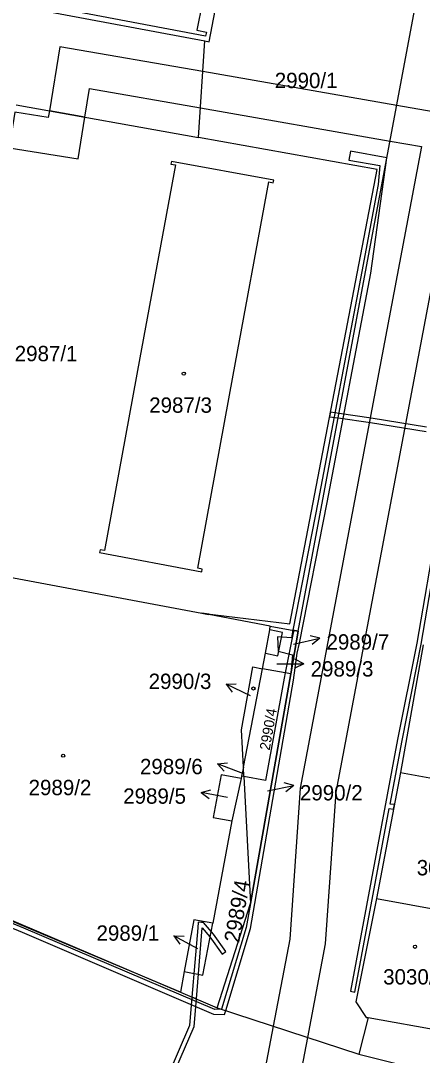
# Model space of a CAD drawing. Extents: x -756746 to -753363, y -1166406 to -1161727.
# Drawn here: x -755238.8 to -755194.3, y -1165348.4 to -1165233.9 of the extents above; entities that cross this region are included whole.
import ezdxf

# ---------------------------------------------------------------- set-up
doc = ezdxf.new("R2010")
doc.units = 0
for name, color, linetype in [('Hranice parcel', 7, 'Continuous'), ('Parcelní čísla', 7, 'Continuous'), ('Pop  PČ popisy', 7, 'Continuous'), ('Vnitřní kresba', 7, 'Continuous'), ('Věcná břemena k části', 7, 'Continuous'), ('Značky budov', 7, 'Continuous')]:
    doc.layers.add(name, color=color, linetype=linetype)

msp = doc.modelspace()

# ---------------------------------------------------------------- linework, layer by layer
at = {"layer": 'Hranice parcel'}
for p, q in [((-755208.07, -1165301.48), (-755195.18, -1165232.73)), ((-755219.11, -1165246.8), (-755218.43, -1165236.08)), ((-755239.33, -1165243.19), (-755219.11, -1165246.8)), ((-755247.99, -1165294), (-755218.74, -1165299.48)), ((-755211.17, -1165300.9), (-755218.74, -1165299.48)), ((-755211.22, -1165301.3), (-755211.17, -1165300.9)), ((-755211.17, -1165300.9), (-755208.57, -1165301.39)), ((-755208.9, -1165306.2), (-755208.07, -1165301.48)), ((-755208.07, -1165301.48), (-755208.57, -1165301.39)), ((-755194.22, -1165302.99), (-755196.74, -1165317.11)), ((-755214.15, -1165316.52), (-755212.03, -1165305.62)), ((-755213.36, -1165331.64), (-755208.9, -1165306.2)), ((-755209.51, -1165306.09), (-755212.03, -1165305.62)), ((-755208.9, -1165306.2), (-755209.51, -1165306.09)), ((-755214.15, -1165316.52), (-755214.35, -1165317.54)), ((-755214.09, -1165317.58), (-755214.15, -1165316.52)), ((-755214.4, -1165317.78), (-755215.44, -1165322.49)), ((-755214.35, -1165317.54), (-755214.4, -1165317.78)), ((-755214.09, -1165317.58), (-755214.35, -1165317.54)), ((-755214.09, -1165317.58), (-755213.36, -1165331.64)), ((-755196.74, -1165317.11), (-755199.39, -1165331.06)), ((-755215.44, -1165322.49), (-755217.54, -1165333.82)), ((-755217.05, -1165343.17), (-755213.36, -1165331.64)), ((-755220.7, -1165339.16), (-755221.13, -1165341.45)), ((-755221.13, -1165341.45), (-755217.05, -1165343.17)), ((-755217.05, -1165343.17), (-755201.37, -1165348.31)), ((-755201.37, -1165348.31), (-755184.78, -1165352.45))]:
    msp.add_line(p, q, dxfattribs=at)
for points in [[(-755215.57, -1165223.82), (-755214.31, -1165217.18), (-755232.9, -1165213.53), (-755236.61, -1165232.68), (-755218.43, -1165236.08)], [(-755218.43, -1165236.08), (-755217.92, -1165236.18), (-755215.57, -1165223.82)], [(-755218.74, -1165299.48), (-755209, -1165300.66), (-755199.33, -1165250.34), (-755219.11, -1165246.8)], [(-755211.33, -1165251.71), (-755210.84, -1165251.8), (-755210.78, -1165251.51), (-755222.11, -1165249.44), (-755222.17, -1165249.74), (-755221.68, -1165249.82), (-755225.61, -1165271.18), (-755229.54, -1165292.53), (-755230.03, -1165292.45), (-755230.09, -1165292.74), (-755218.76, -1165294.89), (-755218.7, -1165294.59), (-755219.2, -1165294.5), (-755215.27, -1165273.11), (-755211.33, -1165251.71)], [(-755252.61, -1165293.14), (-755254.82, -1165292.77), (-755254.61, -1165291.61), (-755260.25, -1165290.56), (-755260.48, -1165291.83), (-755272.55, -1165289.58), (-755272.53, -1165289.46), (-755280.36, -1165288), (-755280.39, -1165288.11), (-755287.48, -1165286.77), (-755287.69, -1165287.92), (-755287.95, -1165287.88), (-755288.05, -1165288.42), (-755290.9, -1165303.66), (-755292.09, -1165311.29), (-755257.06, -1165326.15), (-755221.13, -1165341.45)], [(-755212.03, -1165305.62), (-755211.7, -1165303.92), (-755210.34, -1165304.18), (-755209.8, -1165301.61), (-755211.22, -1165301.3)], [(-755208.57, -1165301.39), (-755208.65, -1165301.83), (-755209.51, -1165306.09)], [(-755214.15, -1165316.52), (-755214.37, -1165312.4), (-755213.08, -1165305.42), (-755212.03, -1165305.62)], [(-755209.51, -1165306.09), (-755209.62, -1165306.67), (-755211.71, -1165318.02), (-755214.09, -1165317.58)], [(-755221.13, -1165341.45), (-755254.32, -1165327.49), (-755292.48, -1165311.65)], [(-755214.4, -1165317.78), (-755216.62, -1165317.37), (-755217.48, -1165322.11), (-755215.44, -1165322.49)], [(-755196.74, -1165317.11), (-755185.38, -1165319.17), (-755184.13, -1165319.39), (-755182.45, -1165319.72), (-755176.65, -1165320.86), (-755173.46, -1165321.33), (-755170.61, -1165321.75)], [(-755199.39, -1165331.06), (-755201.67, -1165342.5), (-755200.54, -1165344.24), (-755200.31, -1165344.26), (-755201.37, -1165348.31)], [(-755199.39, -1165331.06), (-755191.7, -1165332.46), (-755188.08, -1165333.12), (-755185.23, -1165333.69), (-755184.75, -1165333.56)], [(-755217.54, -1165333.82), (-755219.62, -1165333.43), (-755220.7, -1165339.16)], [(-755220.7, -1165339.16), (-755218.62, -1165339.55), (-755217.54, -1165333.82)]]:
    msp.add_lwpolyline(points, dxfattribs=at)
at = {"layer": 'Pop  PČ popisy'}
for p, q in [((-755208.6, -1165302.91), (-755205.68, -1165302.24)), ((-755205.68, -1165302.24), (-755206.76, -1165301.97)), ((-755205.68, -1165302.24), (-755206.54, -1165302.95)), ((-755210.44, -1165305.07), (-755207.44, -1165305.07)), ((-755207.44, -1165305.07), (-755208.44, -1165304.57)), ((-755207.44, -1165305.07), (-755208.44, -1165305.57)), ((-755216.07, -1165307.34), (-755214.95, -1165307.31)), ((-755213.35, -1165308.61), (-755216.07, -1165307.34)), ((-755216.07, -1165307.34), (-755215.37, -1165308.22)), ((-755217.01, -1165316.16), (-755215.9, -1165316.05)), ((-755214.21, -1165317.23), (-755217.01, -1165316.16)), ((-755217.01, -1165316.16), (-755216.26, -1165316.98)), ((-755218.84, -1165319.33), (-755217.76, -1165319.03)), ((-755211.49, -1165319.14), (-755208.54, -1165318.57)), ((-755208.54, -1165318.57), (-755209.62, -1165318.27)), ((-755208.54, -1165318.57), (-755209.43, -1165319.25)), ((-755215.89, -1165319.9), (-755218.84, -1165319.33)), ((-755218.84, -1165319.33), (-755217.95, -1165320.01)), ((-755219.19, -1165336.63), (-755221.84, -1165335.22)), ((-755221.84, -1165335.22), (-755220.72, -1165335.25)), ((-755221.84, -1165335.22), (-755221.19, -1165336.13))]:
    msp.add_line(p, q, dxfattribs=at)
at = {"layer": 'Vnitřní kresba'}
for p, q in [((-755218.68, -1165231.81), (-755219.29, -1165234.92)), ((-755218.34, -1165235.56), (-755235.94, -1165232.26)), ((-755219.29, -1165234.92), (-755218.25, -1165235.12)), ((-755218.25, -1165235.12), (-755218.34, -1165235.56)), ((-755211.7, -1165303.92), (-755211.22, -1165301.3)), ((-755200.31, -1165344.26), (-755192.08, -1165345.73))]:
    msp.add_line(p, q, dxfattribs=at)
at = {"layer": 'Věcná břemena k části'}
for points in [[(-755228.32, -1165449.49), (-755213.31, -1165370.15), (-755218.48, -1165369.17), (-755217.54, -1165364.22), (-755210.64, -1165365.54), (-755209.98, -1165362.1), (-755207, -1165346.46), (-755205.03, -1165336.11), (-755203.87, -1165319.3), (-755189.72, -1165244.55), (-755197.15, -1165243.25), (-755218.65, -1165239.5), (-755234.49, -1165236.74), (-755235.64, -1165243.85)], [(-755231.7, -1165244.55), (-755231.19, -1165241.37), (-755218.9, -1165243.52), (-755197.89, -1165247.18), (-755194.42, -1165247.79), (-755207.85, -1165318.86), (-755209, -1165335.59), (-755210.83, -1165345.21), (-755213.83, -1165360.92), (-755219.88, -1165359.08), (-755220.8, -1165364.01), (-755222.4, -1165372.49), (-755217.98, -1165373.33), (-755233, -1165452.71)], [(-755235.64, -1165243.85), (-755231.7, -1165244.55)], [(-755278.26, -1165318.42), (-755238.67, -1165334.81), (-755217.44, -1165343.87), (-755216.24, -1165343.93), (-755216.1, -1165343.48), (-755213.36, -1165334.39), (-755208.58, -1165306.88), (-755208.19, -1165303.92), (-755207.91, -1165302.81), (-755204.87, -1165287.21), (-755200.03, -1165261.81), (-755198.24, -1165249.03), (-755202.29, -1165248.32), (-755202.46, -1165249.31), (-755199.04, -1165249.9), (-755199.21, -1165251.99), (-755201.01, -1165261.63), (-755205.85, -1165287.03), (-755208.65, -1165301.37), (-755208.07, -1165301.48), (-755208.9, -1165306.2), (-755213.36, -1165331.64), (-755213.84, -1165334.27), (-755216.57, -1165343.33), (-755217.32, -1165343.37), (-755238.47, -1165334.35), (-755278.06, -1165317.96)], [(-755193.85, -1165278.87), (-755200, -1165277.86), (-755203.55, -1165277.36), (-755204.5, -1165277.22), (-755204.59, -1165277.72), (-755203.64, -1165277.85), (-755200.07, -1165278.35), (-755193.89, -1165279.37)], [(-755192.68, -1165289.67), (-755194.93, -1165302.81), (-755197.07, -1165313.47), (-755202.28, -1165341.34), (-755201.79, -1165341.44), (-755197.98, -1165321.12), (-755197.51, -1165321.17), (-755197.42, -1165320.68), (-755197.88, -1165320.63), (-755196.57, -1165313.57), (-755194.44, -1165302.9), (-755192.19, -1165289.76)]]:
    msp.add_lwpolyline(points, dxfattribs=at)
for points in [[(-755235.64, -1165243.85), (-755235.76, -1165244.58), (-755239.46, -1165243.98), (-755240.1, -1165247.93), (-755232.45, -1165249.17), (-755231.7, -1165244.55)], [(-755218.49, -1165299.51), (-755218.74, -1165299.48), (-755218, -1165299.62), (-755217.98, -1165299.57)], [(-755208.9, -1165306.2), (-755208.07, -1165301.48), (-755208.65, -1165301.37), (-755208.81, -1165302.19), (-755210.35, -1165302.1), (-755210.29, -1165303.69), (-755208.72, -1165304.08)], [(-755219.84, -1165342), (-755219.35, -1165342.2), (-755218.7, -1165334.33), (-755217.85, -1165335.32), (-755216.51, -1165337.23), (-755216.1, -1165336.94), (-755217.45, -1165335.02), (-755218.55, -1165333.74), (-755218.78, -1165333.72), (-755219.15, -1165333.69), (-755219.2, -1165334.31)], [(-755223.07, -1165353.27), (-755219.6, -1165345.25), (-755219.35, -1165342.2), (-755219.84, -1165342), (-755220.1, -1165345.13), (-755223.65, -1165353.37), (-755220.77, -1165356.57), (-755220.4, -1165356.24)]]:
    msp.add_lwpolyline(points, close=True, dxfattribs=at)
at = {"layer": 'Značky budov'}
for centre in [(-755220.75, -1165272.94), (-755213.03, -1165307.82), (-755234.11, -1165315.26), (-755195.13, -1165336.42)]:
    msp.add_circle(centre, 0.175, dxfattribs=at)

# ---------------------------------------------------------------- texts
at = {"layer": 'Parcelní čísla'}
for s, p in [('2990/1', (-755210.67, -1165241.32)), ('2987/1', (-755239.48, -1165271.57)), ('2987/3', (-755224.58, -1165277.28)), ('2989/7', (-755204.94, -1165303.51)), ('2989/3', (-755206.69, -1165306.49)), ('2990/3', (-755224.64, -1165307.87)), ('2989/6', (-755225.6, -1165317.31)), ('2989/2', (-755237.94, -1165319.63)), ('2989/5', (-755227.46, -1165320.58)), ('2990/2', (-755207.88, -1165320.21)), ('3028', (-755194.94, -1165328.51)), ('2989/1', (-755230.42, -1165335.75)), ('3030/1', (-755198.66, -1165340.6))]:
    msp.add_text(s, height=1.7, dxfattribs=at).set_placement(p)
for s, height, p in [('2990/4', 1.139, (-755211.24, -1165314.72)), ('2989/4', 1.7, (-755214.62, -1165336.04))]:
    msp.add_text(s, height=height, rotation=80, dxfattribs=at).set_placement(p)

doc.saveas('drawing.dxf')
